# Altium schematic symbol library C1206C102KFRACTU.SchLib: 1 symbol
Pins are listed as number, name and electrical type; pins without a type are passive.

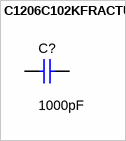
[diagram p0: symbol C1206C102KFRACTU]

## C1206C102KFRACTU
designator C?  ValueDisplayed: 1000pF  (hidden comment: C1206C102KFRACTU)
CAP CER 1000PF 1.5KV X7R 1206; Manufacturer: Kemet; Polarized: N; CompType: Capacitor; U/M: EA; Cap_F: 0.000000001; Tolerance_%: 10; ESR_Ohm: 0.426; Value1: 0.426 ohm; VDC_V: 1500; Value2: 1500V; IRMS_A: 0.189; TaMin_C: -55; TaMax_C: 125; Cap_Case: 1206
signal-integrity model Cap
simulation model Cap
footprint 1206
footprint 1206M
footprint 1206L
pins: 1, 2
